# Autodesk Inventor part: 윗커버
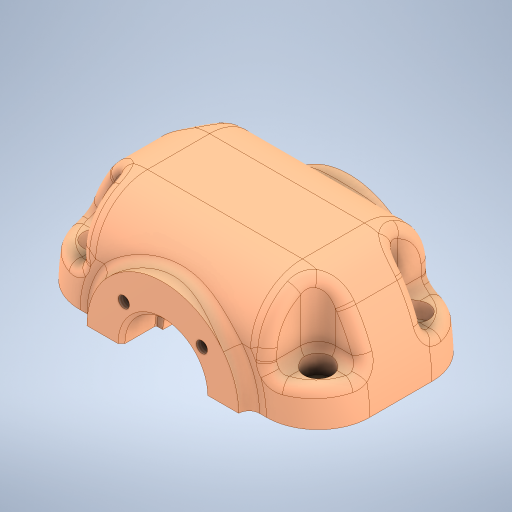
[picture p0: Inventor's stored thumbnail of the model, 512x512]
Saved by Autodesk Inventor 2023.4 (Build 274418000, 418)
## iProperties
Created: 2024-05
Part Number: 윗커버
Material: 알루미늄 6061
Document SubType Name: Modeling
Designer: user
Density: 2.7 g/cm^3
Appearance: 기본값
Sending System: Autodesk Inventor 2025
Preprocessor: ST-DEVELOPER v20
Author: jhkim
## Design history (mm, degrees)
feature "솔리드1"
feature "스레드1" dims "d0" = 8, "d1" = 0
feature "스레드2" dims "d2" = 8, "d3" = 0
feature "스레드3" dims "d4" = 8, "d5" = 0
feature "스레드4" dims "d6" = 8, "d7" = 0
node "솔리드2"
feature "A9D066F2-1C7D-4E18-AEED-F7BC21143FA4" dims "d0" = 8, "d1" = 0
